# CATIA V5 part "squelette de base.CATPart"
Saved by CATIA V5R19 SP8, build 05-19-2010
Part number: squelette base
Bounding box of the stored display mesh (mm): x 0 to 0, y 0 to 39, z -46 to 31
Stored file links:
  C:\Users\rcousturie\Desktop\EU_thinkMotion\iao\IAO_MMS_Groupe1\glenerrant\glenerrant\Nouveau dossier\squelette de base.CATPart
  C:\Users\rcousturie\Desktop\EU_thinkMotion\iao\IAO_MMS_Groupe1\glenerrant\glenerrant\Nouveau dossier\tige verin.CATPart
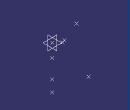
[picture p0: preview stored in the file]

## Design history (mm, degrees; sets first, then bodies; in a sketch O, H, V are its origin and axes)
Set1
  Point1: (0, 0, 0)
  Point2: (0, 26, 31)
  Point3: (0, 39, -12)
  Point4: (0, 0, -14)
  Point5: (0, 0, -34)
  Point6: (0, 0, -46)
  Point7: (0, 11, 6)
  Point8: (0, 13, 9)
Body1 (main body)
